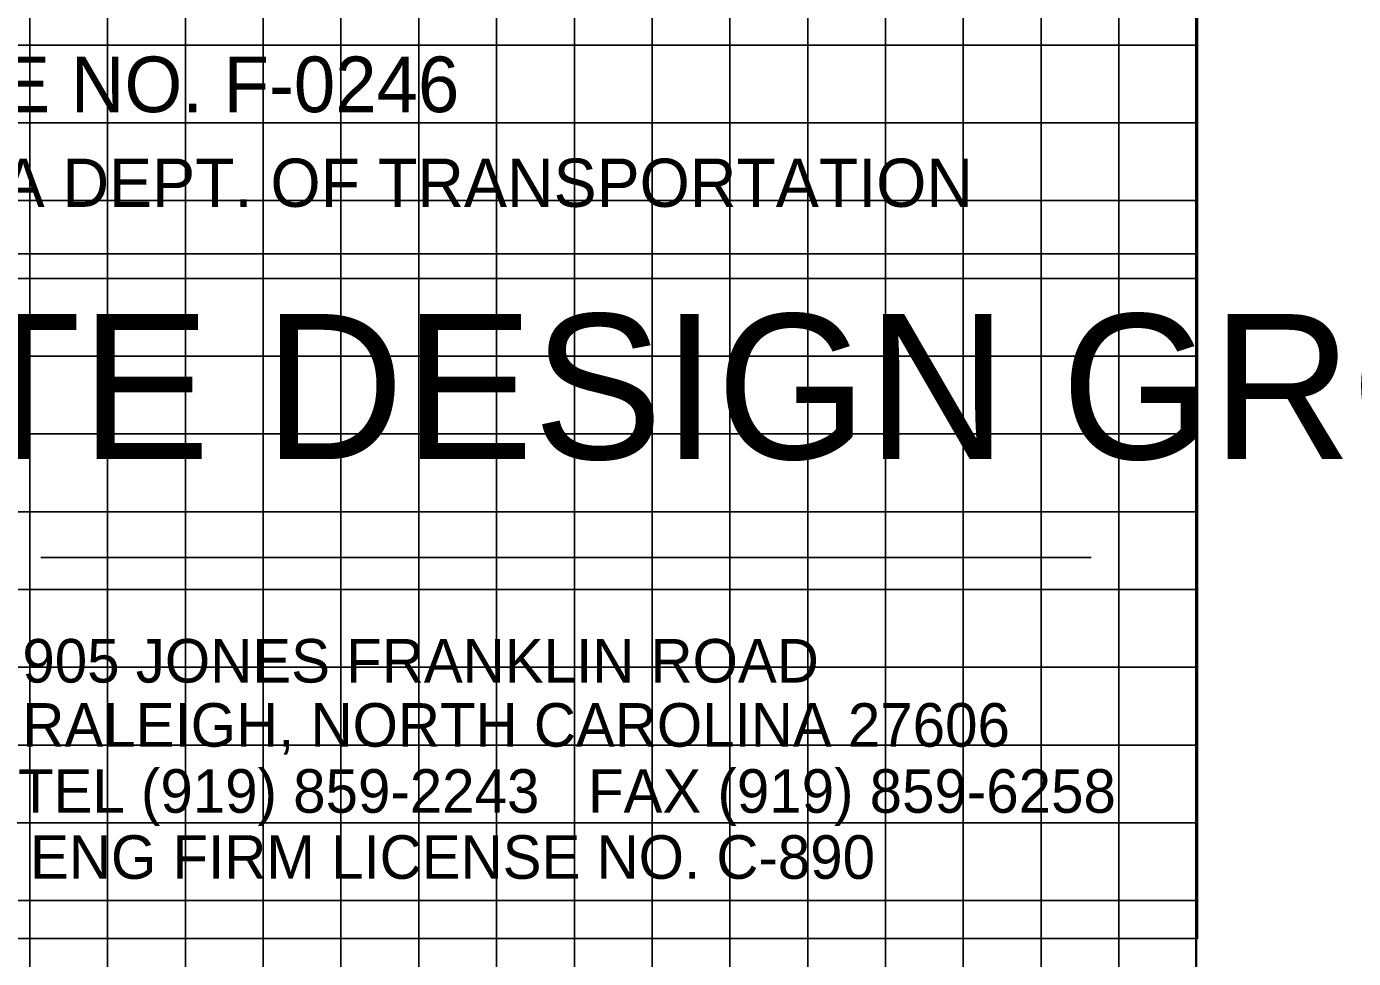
# Model space of a CAD drawing. Extents: x 2186391 to 2188300, y 74582 to 75682.
# Drawn here: x 2187782.5 to 2187867.8, y 75563.6 to 75623.5 of the extents above; entities that cross this region are included whole.
import ezdxf

# ---------------------------------------------------------------- set-up
doc = ezdxf.new("R2010")
doc.units = 0
for name, color, linetype in [('Exist Structure Minor Culvert Topo Terminator', 7, 'Continuous'), ('Exist Structure Minor Footbridge Terminator', 7, 'Continuous'), ('Old_Level_11', 7, 'Continuous'), ('Old_Level_2', 7, 'Continuous'), ('Sheet Cutting Line CELL', 7, 'Continuous'), ('Sheet Plot Border Outside CELL', 7, 'Continuous'), ('Sheet Sticker Exception Certification CELL', 7, 'Continuous')]:
    doc.layers.add(name, color=color, linetype=linetype)

msp = doc.modelspace()

# ---------------------------------------------------------------- linework, layer by layer
at = {"layer": 'Exist Structure Minor Culvert Topo Terminator'}
msp.add_line((2187783.404, 75589.327), (2187850.909, 75589.327), dxfattribs=at)
for points in [[(2187723.339, 75608.852), (2187857.739, 75608.852), (2187857.739, 75657.28), (2187723.339, 75657.28)], [(2187723.339, 75608.852), (2187857.739, 75608.852), (2187857.739, 75564.839), (2187723.339, 75564.839)]]:
    msp.add_lwpolyline(points, close=True, dxfattribs=at)
for start, end in [(0, 180), (180, 0)]:
    msp.add_arc((2187814.179, 75574.438), 0.138, start, end, dxfattribs=at)
at = {"layer": 'Exist Structure Minor Footbridge Terminator'}
for q in [(2187857.739, 75657.28), (2187723.339, 75608.852)]:
    msp.add_line((2187857.739, 75608.852), q, dxfattribs=at)
at = {"layer": 'Old_Level_11'}
for p, q in [((2187807.689, 75157.28), (2187807.689, 75657.28)), ((2187857.639, 75607.28), (2186557.689, 75607.28))]:
    msp.add_line(p, q, dxfattribs=at)
at = {"layer": 'Old_Level_2'}
for points in [[(2187532.689, 75157.28), (2187582.689, 75157.28), (2187582.689, 75657.28), (2187632.689, 75657.28), (2187632.689, 75157.28), (2187682.689, 75157.28), (2187682.689, 75657.28), (2187732.689, 75657.28), (2187732.689, 75157.28), (2187782.689, 75157.28), (2187782.689, 75657.28), (2187832.689, 75657.28), (2187832.689, 75157.28), (2187882.689, 75157.28), (2187882.689, 75496.23)], [(2187857.689, 75582.28), (2186557.689, 75582.28), (2186557.689, 75532.28), (2187857.689, 75532.28)]]:
    msp.add_lwpolyline(points, dxfattribs=at)
at = {"layer": 'Sheet Cutting Line CELL'}
msp.add_lwpolyline([(2187857.639, 75632.23), (2187957.689, 75632.23), (2187957.689, 75519.73), (2187857.639, 75519.73)], close=True, dxfattribs=at)
at = {"layer": 'Sheet Plot Border Outside CELL'}
for points in [[(2187777.689, 75157.28), (2187777.689, 75657.28), (2187787.689, 75657.28), (2187787.689, 75157.28)], [(2187792.689, 75157.28), (2187792.689, 75657.28), (2187797.689, 75657.28), (2187797.689, 75157.28)], [(2187802.689, 75157.28), (2187802.689, 75657.28), (2187812.689, 75657.28), (2187812.689, 75157.28)], [(2187817.689, 75157.28), (2187817.689, 75657.28), (2187822.689, 75657.28), (2187822.689, 75157.28)], [(2187827.689, 75157.28), (2187827.689, 75657.28), (2187837.689, 75657.28), (2187837.689, 75157.28)], [(2187842.689, 75157.28), (2187842.689, 75657.28), (2187847.689, 75657.28), (2187847.689, 75157.28)], [(2187852.689, 75157.28), (2187852.689, 75657.28), (2187862.689, 75657.28)], [(2187857.639, 75622.28), (2186607.689, 75622.28), (2186607.689, 75617.28), (2187857.689, 75617.28)], [(2187857.689, 75612.28), (2186607.689, 75612.28), (2186607.689, 75602.28), (2187857.689, 75602.28)], [(2187857.689, 75597.28), (2186607.689, 75597.28), (2186607.689, 75592.28), (2187857.689, 75592.28)], [(2187857.689, 75587.28), (2186607.689, 75587.28), (2186607.689, 75577.28), (2187857.689, 75577.28)], [(2187857.689, 75572.28), (2186607.689, 75572.28), (2186607.689, 75567.28), (2187857.689, 75567.28)]]:
    msp.add_lwpolyline(points, dxfattribs=at)
at = {"layer": 'Sheet Sticker Exception Certification CELL'}
for points in [[(2187507.689, 75157.28), (2187557.689, 75157.28), (2187557.689, 75657.28), (2187607.689, 75657.28), (2187607.689, 75157.28), (2187657.689, 75157.28), (2187657.689, 75657.28), (2187707.689, 75657.28), (2187707.689, 75157.28), (2187757.689, 75157.28), (2187757.689, 75657.28), (2187807.689, 75657.28), (2187807.689, 75157.28), (2187857.689, 75157.28), (2187857.689, 75657.28), (2187883.989, 75657.28)], [(2186557.689, 75607.28), (2187857.689, 75607.28)]]:
    msp.add_lwpolyline(points, dxfattribs=at)

# ---------------------------------------------------------------- texts
at = {"layer": 'Exist Structure Minor Culvert Topo Terminator'}
for s, height, p in [('SUNGATE DESIGN GROUP, P.A.', 9.31938, (2187734.032, 75595.663)), ('905 JONES FRANKLIN ROAD', 2.80071, (2187782.207, 75581.295)), ('RALEIGH, NORTH CAROLINA 27606', 2.80071, (2187782.207, 75577.173)), ('TEL (919) 859-2243   FAX (919) 859-6258', 2.80071, (2187781.922, 75572.926)), ('ENG FIRM LICENSE NO. C-890', 2.80071, (2187782.701, 75568.679))]:
    msp.add_text(s, height=height, dxfattribs=at).set_placement(p)
at = {"layer": 'Exist Structure Minor Footbridge Terminator'}
for s, height, rotation, p in [('NC LICENSE NO. F-0246', 3.57538, 359.99996, (2187755.296, 75617.962)), ('FOR NORTH CAROLINA DEPT. OF TRANSPORTATION', 3.10128, 359.99995, (2187736.633, 75611.875))]:
    msp.add_text(s, height=height, rotation=rotation, dxfattribs=at).set_placement(p)

doc.saveas('drawing.dxf')
